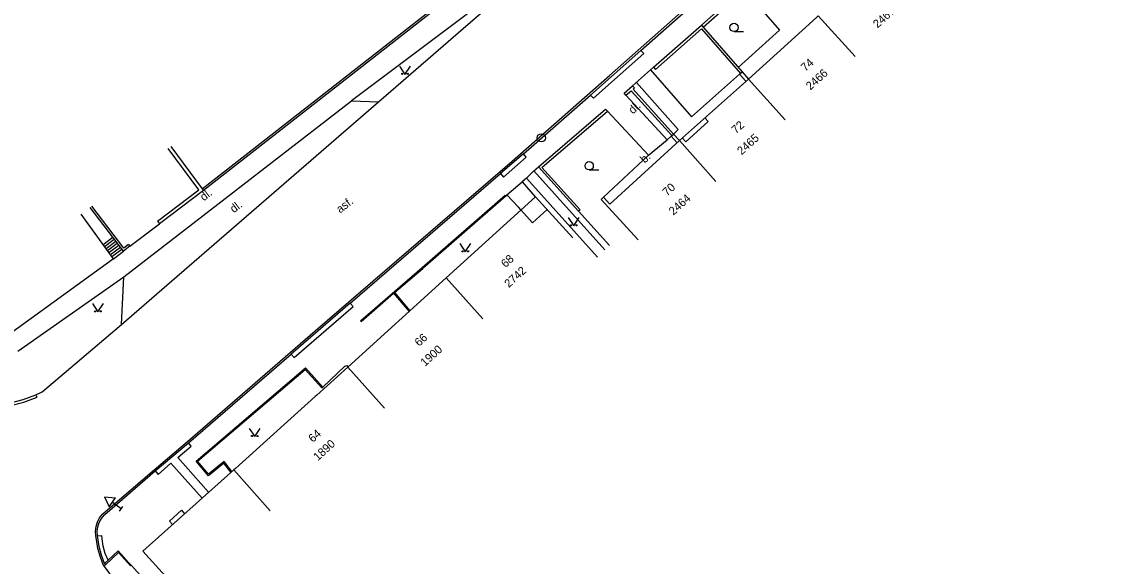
# Model space of a CAD drawing. Extents: x -584400 to -581602, y -1210894 to -1208793.
# Drawn here: x -582418.7 to -582319.7, y -1209464.9 to -1209415.4 of the extents above; entities that cross this region are included whole.
import ezdxf

# ---------------------------------------------------------------- set-up
doc = ezdxf.new("R2010")
doc.units = 0
for name, color, linetype in [('BUDOVY_MĚŘ', 7, 'Continuous'), ('MAP_ZN_BP', 7, 'Continuous'), ('POMOC_POPIS', 7, 'Continuous'), ('ROZHRANÍ_PLOCH', 7, 'Continuous'), ('ZN_DOPLŇKOVÉ', 7, 'Continuous'), ('ZN_KULTUR', 7, 'Continuous'), ('Č_POPIS_EVID', 7, 'Continuous')]:
    doc.layers.add(name, color=color, linetype=linetype)

msp = doc.modelspace()

# ---------------------------------------------------------------- linework, layer by layer
at = {"layer": 'BUDOVY_MĚŘ'}
for points in [[(-582346.14, -1209414.85), (-582346.29, -1209414.99), (-582352.5, -1209420.6)], [(-582346.14, -1209414.85), (-582342.77, -1209418.55)], [(-582352.5, -1209420.6), (-582358.78, -1209426.19)], [(-582352.5, -1209420.6), (-582349.15, -1209424.31)], [(-582365.92, -1209431.56), (-582365.69, -1209431.36), (-582365.11, -1209432), (-582358.78, -1209426.19)], [(-582358.78, -1209426.19), (-582355.46, -1209429.92)], [(-582371.9, -1209431.31), (-582380.04, -1209438.7)], [(-582371.9, -1209431.31), (-582368.48, -1209435.05)], [(-582365.92, -1209431.56), (-582362.53, -1209435.24)], [(-582410.33, -1209436.95), (-582413.26, -1209432.9)], [(-582410.33, -1209436.95), (-582423.25, -1209446.3), (-582427.71, -1209434.13)], [(-582380.04, -1209438.7), (-582388.98, -1209446.82)], [(-582380.04, -1209438.7), (-582376.68, -1209442.41)], [(-582388.98, -1209446.82), (-582391.81, -1209449.37), (-582391.96, -1209449.5), (-582399.23, -1209456.04), (-582399.38, -1209456.17)], [(-582388.98, -1209446.82), (-582385.64, -1209450.54)], [(-582399.38, -1209456.17), (-582407.67, -1209463.58)], [(-582399.38, -1209456.17), (-582396.05, -1209459.9)], [(-582397.34, -1209474.94), (-582401.53, -1209470.33), (-582407.67, -1209463.58)]]:
    msp.add_lwpolyline(points, dxfattribs=at)
at = {"layer": 'MAP_ZN_BP'}
for radius in [0.375, 0.0005]:
    msp.add_circle((-582371.36, -1209425.951), radius, dxfattribs=at)
at = {"layer": 'ROZHRANÍ_PLOCH'}
for points in [[(-582411.27, -1209460.15), (-582406.62, -1209456.16), (-582403.59, -1209453.59), (-582391.95, -1209443.5), (-582374.01, -1209428.06), (-582365.14, -1209420.28), (-582352.37, -1209408.95), (-582339.06, -1209397), (-582326.13, -1209385.36), (-582321.21, -1209380.9), (-582313.38, -1209375.25), (-582301.4, -1209366.6), (-582294.11, -1209360), (-582287.76, -1209351.14), (-582285.39, -1209347.91), (-582279.69, -1209342.63), (-582272.21, -1209335.94), (-582264.86, -1209329.84), (-582259.42, -1209325.45), (-582254.82, -1209321.63), (-582249.41, -1209317.62), (-582247.49, -1209316.56)], [(-582362.3, -1209417.99), (-582354.11, -1209410.75), (-582353.83, -1209411.05), (-582349.26, -1209406.94), (-582349.54, -1209406.66), (-582354.1, -1209410.75)], [(-582375.3, -1209412.54), (-582388.66, -1209422.59)], [(-582352.83, -1209412.52), (-582349.66, -1209416.15), (-582353.42, -1209419.55)], [(-582409.61, -1209442.93), (-582405.91, -1209439.76), (-582376.46, -1209414.23)], [(-582362.3, -1209417.99), (-582366.88, -1209422.05)], [(-582366.88, -1209422.05), (-582366.62, -1209422.35), (-582362.04, -1209418.28), (-582362.3, -1209417.99)], [(-582361.43, -1209419.77), (-582357.67, -1209424.04), (-582353.3, -1209420.14)], [(-582353.3, -1209420.14), (-582353.07, -1209419.95), (-582352.5, -1209420.6)], [(-582352.73, -1209420.8), (-582353.3, -1209420.14)], [(-582362.69, -1209420.91), (-582358.91, -1209425.2), (-582359.31, -1209425.6)], [(-582409.4, -1209438.6), (-582388.66, -1209422.59)], [(-582388.66, -1209422.59), (-582386.19, -1209422.67)], [(-582372.99, -1209427.4), (-582366.88, -1209422.05)], [(-582363.65, -1209422.07), (-582359.89, -1209426.12)], [(-582365.34, -1209423.52), (-582361.6, -1209427.54)], [(-582358.52, -1209425.95), (-582358.2, -1209426.31), (-582356.16, -1209424.47), (-582356.46, -1209424.13)], [(-582359.53, -1209425.81), (-582359.31, -1209425.6)], [(-582359.31, -1209425.6), (-582358.78, -1209426.19)], [(-582361.6, -1209427.54), (-582359.89, -1209426.12)], [(-582359.89, -1209426.12), (-582359.53, -1209425.81)], [(-582359, -1209426.39), (-582359.53, -1209425.81)], [(-582372.99, -1209427.4), (-582375.08, -1209429.19)], [(-582375.08, -1209429.19), (-582374.82, -1209429.52), (-582372.73, -1209427.7), (-582372.99, -1209427.4)], [(-582361.6, -1209427.54), (-582365.69, -1209431.36)], [(-582372.03, -1209428.95), (-582371.62, -1209428.58)], [(-582388.76, -1209440.99), (-582375.08, -1209429.19)], [(-582372.72, -1209429.62), (-582373.11, -1209429.95)], [(-582372.72, -1209429.62), (-582372.03, -1209428.95)], [(-582366.26, -1209436.8), (-582372.72, -1209429.62)], [(-582372.03, -1209428.95), (-582365.57, -1209436.13)], [(-582433.5, -1209430.16), (-582429.52, -1209440.89), (-582426.99, -1209447.8), (-582426.99, -1209447.79), (-582426.67, -1209448.32), (-582426.29, -1209448.81), (-582425.85, -1209449.24), (-582425.36, -1209449.62), (-582424.83, -1209449.93), (-582424.26, -1209450.16), (-582423.84, -1209450.29), (-582422.49, -1209450.48), (-582421.14, -1209450.49), (-582419.8, -1209450.34), (-582418.48, -1209450.01), (-582417.29, -1209449.56), (-582417.39, -1209449.33)], [(-582374.5, -1209431.14), (-582373.11, -1209429.95)], [(-582373.11, -1209429.95), (-582371.93, -1209431.33)], [(-582387.84, -1209442.59), (-582384.71, -1209439.9), (-582382.22, -1209437.76), (-582374.65, -1209431.17), (-582374.57, -1209431.23)], [(-582374.5, -1209431.14), (-582374.57, -1209431.23), (-582382.16, -1209437.84)], [(-582373.23, -1209432.51), (-582373.45, -1209432.27), (-582374.5, -1209431.14)], [(-582373.23, -1209432.51), (-582372.17, -1209433.68)], [(-582370.84, -1209432.46), (-582372.17, -1209433.68)], [(-582411.27, -1209435.65), (-582410.4, -1209434.98)], [(-582411.14, -1209435.83), (-582410.26, -1209435.17)], [(-582411, -1209436.02), (-582410.12, -1209435.35)], [(-582410.87, -1209436.21), (-582409.98, -1209435.53)], [(-582410.74, -1209436.39), (-582409.84, -1209435.72)], [(-582410.6, -1209436.58), (-582409.7, -1209435.9)], [(-582410.47, -1209436.76), (-582409.56, -1209436.08)], [(-582410.33, -1209436.95), (-582409.43, -1209436.26)], [(-582419.04, -1209445.36), (-582409.4, -1209438.6)], [(-582409.61, -1209442.93), (-582409.4, -1209438.6)], [(-582384.74, -1209440.03), (-582382.16, -1209437.84)], [(-582387.84, -1209442.59), (-582387.77, -1209442.65), (-582384.82, -1209440.1)], [(-582384.74, -1209440.03), (-582384.82, -1209440.1)], [(-582384.82, -1209440.1), (-582383.4, -1209441.76)], [(-582384.8, -1209440.09), (-582384.74, -1209440.03)], [(-582384.74, -1209440.03), (-582383.33, -1209441.69)], [(-582388.76, -1209440.99), (-582394.15, -1209445.65)], [(-582394.15, -1209445.65), (-582393.87, -1209445.94), (-582388.49, -1209441.3), (-582388.76, -1209440.99)], [(-582417.39, -1209449.33), (-582416.81, -1209449.06), (-582409.61, -1209442.93)], [(-582403.49, -1209453.7), (-582394.15, -1209445.65)], [(-582399.63, -1209456.39), (-582400.28, -1209455.55), (-582401.68, -1209456.71), (-582402.8, -1209455.39), (-582392.85, -1209446.89), (-582391.27, -1209448.63)], [(-582399.55, -1209456.32), (-582400.26, -1209455.41), (-582401.67, -1209456.57), (-582402.67, -1209455.39), (-582392.86, -1209447.03), (-582391.34, -1209448.7), (-582391.27, -1209448.63)], [(-582391.27, -1209448.63), (-582389.26, -1209446.72), (-582389.08, -1209446.66), (-582388.98, -1209446.82)], [(-582423.84, -1209450.04), (-582423.79, -1209450.05), (-582422.48, -1209450.23), (-582421.15, -1209450.24), (-582419.84, -1209450.09), (-582418.56, -1209449.77), (-582417.39, -1209449.33)], [(-582406.52, -1209456.27), (-582403.49, -1209453.7)], [(-582401.66, -1209458.21), (-582404.46, -1209455.04), (-582403.24, -1209454), (-582403.49, -1209453.7)], [(-582411.78, -1209462.16), (-582411.81, -1209461.75), (-582411.76, -1209461.34), (-582411.63, -1209460.95), (-582411.43, -1209460.59), (-582411.16, -1209460.27), (-582411.12, -1209460.23), (-582406.52, -1209456.27)], [(-582406.52, -1209456.27), (-582406.26, -1209456.58), (-582405.1, -1209455.57), (-582402.26, -1209458.74)], [(-582411.23, -1209464.88), (-582411.52, -1209464.11), (-582411.75, -1209463.32), (-582411.89, -1209462.52), (-582411.93, -1209462.17), (-582411.97, -1209461.75), (-582411.92, -1209461.32), (-582411.79, -1209460.91), (-582411.59, -1209460.54), (-582411.32, -1209460.2), (-582411.23, -1209460.11)], [(-582404.96, -1209461.15), (-582405.23, -1209460.84), (-582404.13, -1209459.85), (-582403.85, -1209460.16)], [(-582411.78, -1209462.16), (-582411.38, -1209462.13)], [(-582411.14, -1209464.7), (-582411.42, -1209463.94), (-582411.63, -1209463.15), (-582411.76, -1209462.35), (-582411.78, -1209462.16)], [(-582410.82, -1209464.4), (-582411.08, -1209463.77), (-582411.26, -1209463.12), (-582411.36, -1209462.45), (-582411.38, -1209462.13)], [(-582409.87, -1209463.68), (-582411.07, -1209464.81)], [(-582409.89, -1209463.53), (-582410.82, -1209464.4)], [(-582409.89, -1209463.53), (-582408.96, -1209464.6)], [(-582409.87, -1209463.68), (-582408.79, -1209464.91)], [(-582411.23, -1209464.88), (-582411.07, -1209464.81)], [(-582411.23, -1209464.88), (-582410.4, -1209466.01), (-582409.94, -1209466.59), (-582400.57, -1209477.09), (-582397.8, -1209480.16), (-582390.08, -1209488.74), (-582388.84, -1209490.16), (-582360.6, -1209522.5), (-582340.8, -1209546.53), (-582320.81, -1209567.67)], [(-582411.14, -1209464.7), (-582410.82, -1209464.4)], [(-582411.14, -1209464.7), (-582411.07, -1209464.81)], [(-582408.73, -1209464.85), (-582408.96, -1209464.6)], [(-582408.73, -1209464.85), (-582408.79, -1209464.91)], [(-582408.73, -1209464.85), (-582398.97, -1209475.64), (-582400.57, -1209477.09)]]:
    msp.add_lwpolyline(points, dxfattribs=at)
at = {"layer": 'ZN_DOPLŇKOVÉ'}
for p, q in [((-582411.135, -1209458.62), (-582410.724, -1209459.532)), ((-582411.135, -1209458.62), (-582410.14, -1209458.72)), ((-582410.724, -1209459.532), (-582410.14, -1209458.72)), ((-582409.62, -1209459.71), (-582410.432, -1209459.126)), ((-582409.766, -1209459.913), (-582409.474, -1209459.507))]:
    msp.add_line(p, q, dxfattribs=at)
for points in [[(-582402.24, -1209430.59), (-582376.83, -1209410.71)], [(-582376.75, -1209410.9), (-582402.12, -1209430.75)], [(-582356.77, -1209415.7), (-582353, -1209412.33), (-582352.83, -1209412.52)], [(-582356.61, -1209415.89), (-582352.83, -1209412.52)], [(-582361.14, -1209419.51), (-582356.77, -1209415.7), (-582356.61, -1209415.89)], [(-582361.14, -1209419.51), (-582360.96, -1209419.72), (-582356.76, -1209416.02), (-582353.22, -1209420.08)], [(-582356.61, -1209415.89), (-582353.07, -1209419.95)], [(-582361.14, -1209419.51), (-582363.05, -1209421.23)], [(-582363.65, -1209422.07), (-582363.82, -1209421.89), (-582363.05, -1209421.23), (-582362.88, -1209421.41), (-582363.01, -1209421.53), (-582359.31, -1209425.6)], [(-582363.65, -1209422.07), (-582363.17, -1209421.66), (-582359.46, -1209425.74)], [(-582367.98, -1209432.62), (-582371.62, -1209428.58), (-582365.51, -1209423.34), (-582365.34, -1209423.52)], [(-582367.83, -1209432.49), (-582371.3, -1209428.64), (-582365.34, -1209423.52)], [(-582405.12, -1209426.75), (-582402.24, -1209430.59)], [(-582406.32, -1209433.53), (-582402.54, -1209430.69), (-582405.36, -1209426.93)], [(-582402.24, -1209430.59), (-582402.12, -1209430.75), (-582406.14, -1209433.77)], [(-582408.95, -1209435.65), (-582408.83, -1209435.81), (-582409.43, -1209436.26), (-582412.44, -1209432.28)], [(-582408.95, -1209435.65), (-582409.39, -1209435.99), (-582412.29, -1209432.16)], [(-582367.83, -1209432.49), (-582367.98, -1209432.62)], [(-582367.98, -1209432.62), (-582365.16, -1209435.76)], [(-582406.32, -1209433.53), (-582406.14, -1209433.77)], [(-582408.83, -1209435.81), (-582406.14, -1209433.77)]]:
    msp.add_lwpolyline(points, dxfattribs=at)
at = {"layer": 'ZN_KULTUR'}
for p, q in [((-582353.81, -1209416.275), (-582352.935, -1209416.275)), ((-582367, -1209428.865), (-582366.125, -1209428.865))]:
    msp.add_line(p, q, dxfattribs=at)
for points in [[(-582384.28, -1209419.42), (-582383.78, -1209420.17), (-582383.28, -1209419.42)], [(-582368.91, -1209433.21), (-582368.41, -1209433.96), (-582367.91, -1209433.21)], [(-582378.79, -1209435.58), (-582378.29, -1209436.33), (-582377.79, -1209435.58)], [(-582412.25, -1209441.04), (-582411.75, -1209441.79), (-582411.25, -1209441.04)], [(-582397.96, -1209452.39), (-582397.46, -1209453.14), (-582396.96, -1209452.39)]]:
    msp.add_lwpolyline(points, dxfattribs=at)
for centre, radius in [((-582353.81, -1209415.9), 0.375), ((-582384.03, -1209420.12), 0.05), ((-582383.53, -1209420.12), 0.05), ((-582367, -1209428.49), 0.375), ((-582368.66, -1209433.91), 0.05), ((-582368.16, -1209433.91), 0.05), ((-582378.54, -1209436.28), 0.05), ((-582378.04, -1209436.28), 0.05), ((-582412, -1209441.74), 0.05), ((-582411.5, -1209441.74), 0.05), ((-582397.71, -1209453.09), 0.05), ((-582397.21, -1209453.09), 0.05)]:
    msp.add_circle(centre, radius, dxfattribs=at)

# ---------------------------------------------------------------- texts
at = {"layer": 'POMOC_POPIS'}
for s, rotation, p in [('dl.', 42.82057, (-582363.02, -1209423.83)), ('b.', 42.51043, (-582361.95, -1209428.31)), ('dl.', 37.6659, (-582402.1, -1209431.74)), ('asf.', 37.6659, (-582389.69, -1209432.85)), ('dl.', 37.6659, (-582399.37, -1209432.82))]:
    msp.add_text(s, height=0.75, rotation=rotation, dxfattribs=at).set_placement(p)
at = {"layer": 'Č_POPIS_EVID'}
for s, rotation, p in [('2467', 41.95976, (-582340.74, -1209416)), ('74', 42.07957, (-582347.31, -1209419.95)), ('2466', 41.95976, (-582346.86, -1209421.65)), ('72', 41.65168, (-582353.64, -1209425.63)), ('2465', 41.95976, (-582353.12, -1209427.55)), ('70', 42.55592, (-582359.91, -1209431.3)), ('2464', 41.95976, (-582359.34, -1209433.04)), ('68', 42.4332, (-582374.62, -1209437.81)), ('2742', 42.13434, (-582374.32, -1209439.63)), ('66', 42.24051, (-582382.49, -1209444.98)), ('1900', 42.13434, (-582381.96, -1209446.8)), ('64', 41.95403, (-582392.17, -1209453.72)), ('1890', 42.13434, (-582391.72, -1209455.39))]:
    msp.add_text(s, height=0.75, rotation=rotation, dxfattribs=at).set_placement(p)

doc.saveas('drawing.dxf')
